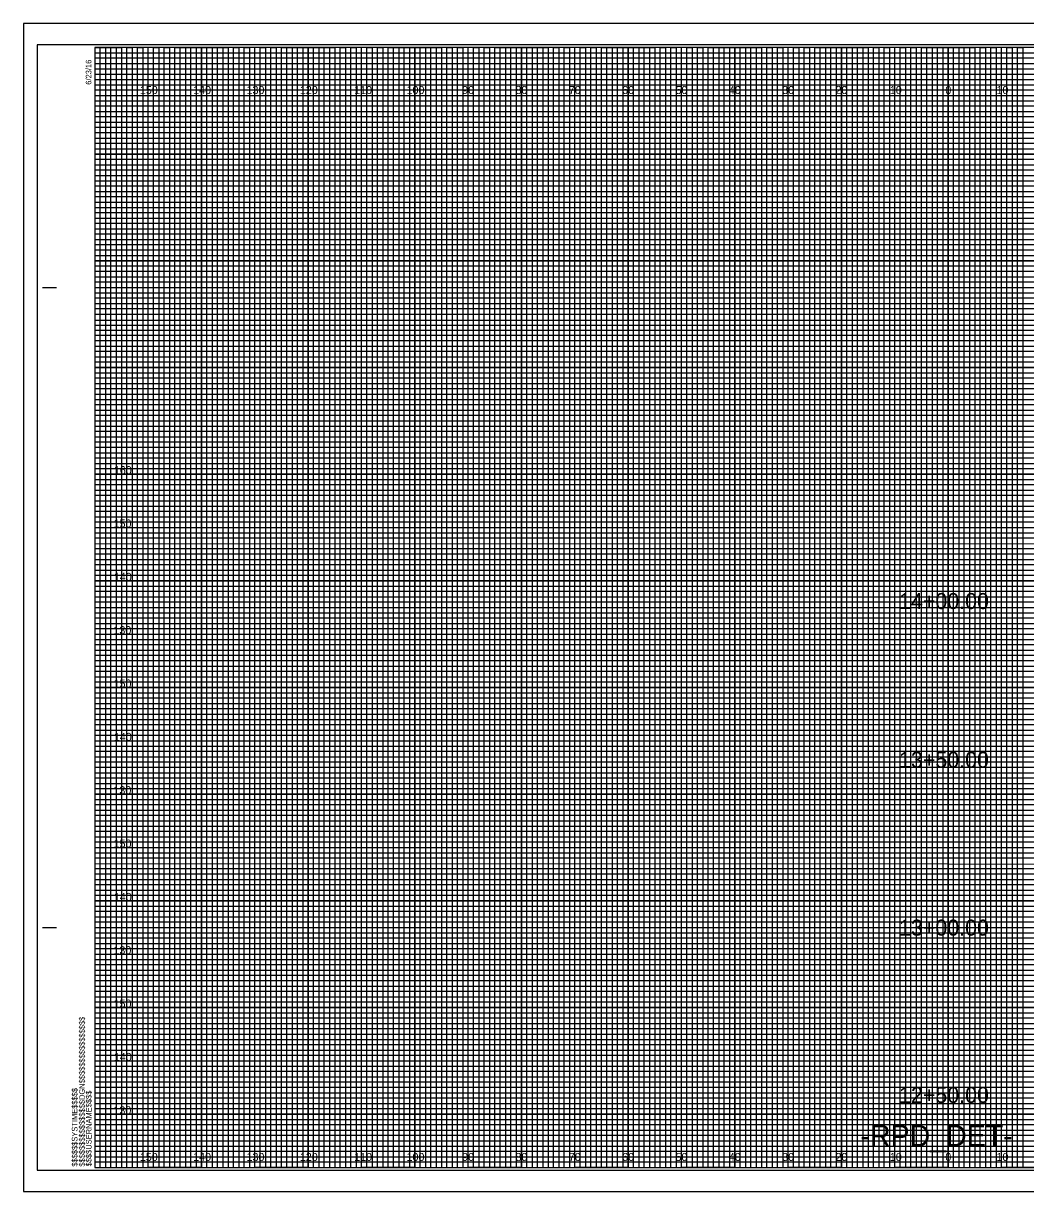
# Model space of a CAD drawing. Extents: x -13 to 323, y -5 to 434.
# Drawn here: x -13.4 to 174.5, y 215.5 to 434.5 of the extents above; entities that cross this region are included whole.
import ezdxf

# ---------------------------------------------------------------- set-up
doc = ezdxf.new("R2010")
doc.units = 0
for name, color, linetype in [('Exist Cross Section Cell', 7, 'Continuous'), ('Exist XS Center Line Elevation Label', 7, 'Continuous'), ('Exist XS Ground Line', 7, 'Continuous'), ('Prop CMT Pvmt Course 1', 7, 'Continuous'), ('Prop CMT Pvmt Course 3', 7, 'Continuous'), ('Prop CMT Pvmt Surface', 7, 'Continuous'), ('Prop CMT Pvmt Surface Shoulder', 7, 'Continuous'), ('Prop CMT Shld Paved Course 1', 7, 'Continuous'), ('Prop CMT Shld Paved Course 2', 7, 'Continuous'), ('Prop CMT Shld Paved Course 3', 7, 'Continuous'), ('Prop CMT Slope Grass', 7, 'Continuous'), ('Prop CMT Subgrade Earthwork', 7, 'Continuous'), ('Scratch_Level_1', 7, 'Continuous')]:
    doc.layers.add(name, color=color, linetype=linetype)

msp = doc.modelspace()

# ---------------------------------------------------------------- linework, layer by layer
at = {"layer": 'Exist XS Center Line Elevation Label'}
for points in [[(0, 430), (5, 430), (5, 220), (15, 220), (15, 430), (25, 430), (25, 220), (35, 220), (35, 430), (45, 430), (45, 220), (55, 220), (55, 430), (65, 430), (65, 220), (75, 220), (75, 430), (85, 430), (85, 220), (95, 220), (95, 430), (105, 430), (105, 220), (115, 220), (115, 430), (125, 430), (125, 220), (135, 220), (135, 430), (145, 430), (145, 220), (155, 220), (155, 430), (165, 430), (165, 220), (175, 220)], [(0, 425), (275, 425)], [(0, 405), (320, 405), (320, 415), (0, 415)], [(0, 385), (320, 385), (320, 395), (0, 395)], [(0, 365), (320, 365), (320, 375), (0, 375)], [(0, 345), (320, 345), (320, 355), (0, 355)], [(0, 325), (320, 325), (320, 335), (0, 335)], [(0, 305), (320, 305), (320, 315), (0, 315)], [(0, 285), (320, 285), (320, 295), (0, 295)], [(0, 265), (320, 265), (320, 275), (0, 275)], [(0, 245), (320, 245), (320, 255), (0, 255)], [(0, 225), (320, 225), (320, 235), (0, 235)]]:
    msp.add_lwpolyline(points, dxfattribs=at)
at = {"layer": 'Exist XS Ground Line'}
for p, q in [((10, 430), (0, 430)), ((10, 220), (10, 430)), ((30, 430), (20, 430)), ((20, 430), (20, 220)), ((30, 220), (30, 430)), ((50, 430), (40, 430)), ((40, 430), (40, 220)), ((50, 220), (50, 430)), ((70, 430), (60, 430)), ((60, 430), (60, 220)), ((70, 220), (70, 430)), ((90, 430), (80, 430)), ((80, 430), (80, 220)), ((90, 220), (90, 430)), ((110, 430), (100, 430)), ((100, 430), (100, 220)), ((110, 220), (110, 430)), ((130, 430), (120, 430)), ((120, 430), (120, 220)), ((130, 220), (130, 430)), ((150, 430), (140, 430)), ((140, 430), (140, 220)), ((150, 220), (150, 430)), ((170, 430), (160, 430)), ((160, 430), (160, 220)), ((170, 220), (170, 430)), ((20, 220), (10, 220)), ((40, 220), (30, 220)), ((60, 220), (50, 220)), ((80, 220), (70, 220)), ((100, 220), (90, 220)), ((120, 220), (110, 220)), ((140, 220), (130, 220)), ((160, 220), (150, 220)), ((180, 220), (170, 220))]:
    msp.add_line(p, q, dxfattribs=at)
for points in [[(0, 420), (320, 420), (320, 410), (0, 410)], [(0, 400), (320, 400), (320, 390), (0, 390)], [(0, 380), (320, 380), (320, 370), (0, 370)], [(0, 360), (320, 360), (320, 350), (0, 350)], [(0, 340), (320, 340), (320, 330), (0, 330)], [(0, 320), (320, 320), (320, 310), (0, 310)], [(0, 300), (320, 300), (320, 290), (0, 290)], [(0, 280), (320, 280), (320, 270), (0, 270)], [(0, 260), (320, 260), (320, 250), (0, 250)], [(0, 240), (320, 240), (320, 230), (0, 230)]]:
    msp.add_lwpolyline(points, dxfattribs=at)
at = {"layer": 'Prop CMT Pvmt Course 3'}
msp.add_lwpolyline([(-13.4, 215.5), (323.3, 215.5), (323.3, 434.5), (-13.4, 434.5)], close=True, dxfattribs=at)
at = {"layer": 'Prop CMT Pvmt Surface'}
for p, q in [((10, 220), (10, 430)), ((20, 220), (20, 430)), ((30, 220), (30, 430)), ((40, 220), (40, 430)), ((50, 220), (50, 430)), ((60, 220), (60, 430)), ((70, 220), (70, 430)), ((80, 220), (80, 430)), ((90, 220), (90, 430)), ((100, 220), (100, 430)), ((110, 220), (110, 430)), ((120, 220), (120, 430)), ((130, 220), (130, 430)), ((140, 220), (140, 430)), ((150, 220), (150, 430)), ((160, 220), (160, 430)), ((170, 220), (170, 430)), ((0, 420), (320, 420)), ((0, 410), (320, 410)), ((0, 400), (320, 400)), ((0, 390), (320, 390)), ((0, 380), (320, 380)), ((0, 370), (320, 370)), ((0, 360), (320, 360)), ((0, 350), (320, 350)), ((0, 340), (320, 340)), ((0, 330), (320, 330)), ((0, 320), (320, 320)), ((0, 310), (320, 310)), ((0, 300), (320, 300)), ((0, 290), (320, 290)), ((0, 280), (320, 280)), ((0, 270), (320, 270)), ((0, 260), (320, 260)), ((0, 250), (320, 250)), ((0, 240), (320, 240)), ((0, 230), (320, 230))]:
    msp.add_line(p, q, dxfattribs=at)
at = {"layer": 'Prop CMT Pvmt Surface Shoulder'}
for p, q in [((323.3, 434.5), (-13.4, 434.5)), ((-13.4, 434.5), (-13.4, 215.5)), ((-13.4, 215.5), (323.3, 215.5))]:
    msp.add_line(p, q, dxfattribs=at)
at = {"layer": 'Prop CMT Shld Paved Course 1'}
for p, q in [((0, 429), (260, 429)), ((260, 427.98), (0, 427.98)), ((0, 427.98), (0, 427)), ((0, 427), (260, 427)), ((260, 425.89), (0, 425.89)), ((0, 425.89), (0, 424)), ((0, 424), (320, 424))]:
    msp.add_line(p, q, dxfattribs=at)
for points in [[(0, 423), (270, 423), (320, 423), (320, 422), (0, 422)], [(0, 421), (320, 421), (320, 419), (0, 419)], [(0, 418), (320, 418), (320, 417), (0, 416.98)], [(0, 416), (320, 416), (320, 414), (0, 414)], [(0, 413), (320, 413), (320, 412), (0, 412)], [(0, 411), (320, 411), (320, 409), (0, 409)], [(0, 408), (320, 408), (320, 407), (0, 407)], [(0, 406), (320, 406), (320, 404), (0, 404)], [(0, 403), (320, 403), (320, 402), (0, 402)], [(0, 401), (320, 401), (320, 399), (0, 399)], [(0, 398), (320, 398), (320, 397), (0, 397)], [(0, 396), (320, 396), (320, 393.95), (320, 393), (320, 392), (0, 392)], [(0, 394), (320, 394), (320, 393), (0, 393)], [(0, 391), (320, 391), (320, 389), (0, 389.03)], [(0, 389.03), (320, 389), (320, 388), (0, 388)], [(0, 387), (320, 387), (320, 386), (0, 386)], [(0, 384), (320, 384), (320, 383), (0, 383)], [(0, 382), (320, 382), (320, 381), (0, 381)], [(-0.07, 378.89), (320, 378.89), (320, 377.88), (-0.07, 377.88)], [(0, 377), (320, 377), (320, 376), (0, 376)], [(0, 374), (320, 374), (320, 373), (0, 373)], [(0, 372), (320, 372), (320, 371), (0, 371)], [(0, 369), (320, 369), (320, 368), (0, 368)], [(0, 367), (320, 367), (320, 366), (0, 366)], [(0, 364), (320, 364), (320, 363), (0, 363)], [(0, 362), (320, 362), (320, 361), (0, 361)], [(0, 359), (320, 359), (319.99, 357.98), (0, 358)], [(0, 357), (320, 357), (320, 356), (0, 356)], [(0, 354), (320, 354), (320, 353), (0, 353)], [(0, 352), (320, 352), (320, 351), (0, 351)], [(0, 349), (320, 349), (320, 348), (0, 348)], [(0, 347), (320, 347), (320, 346), (0, 346)], [(0, 344), (320, 344), (320, 343), (0, 343)], [(0, 342), (320, 342), (320, 341), (0, 341)], [(0, 339), (320, 339), (320, 338), (0, 338)], [(0, 336.99), (320.07, 336.91), (320, 336), (0, 336)], [(0, 334), (320, 334), (320, 333), (0, 333)], [(0, 332), (320, 332), (320, 331), (0, 331)], [(0, 329), (320, 329), (320, 328), (0, 328)], [(0, 327), (320, 327), (320, 326), (0, 326)], [(0, 324), (320, 324), (320, 323), (0, 323)], [(0, 322), (320, 322), (320, 321), (0, 321)], [(0, 319), (320, 319), (320, 318), (0, 318)], [(0, 317), (320, 317), (320, 316), (0, 316)], [(0, 314), (320, 314), (320, 313), (0, 313)], [(0, 312), (320, 312), (320, 311), (0, 311)], [(0, 309), (320, 309), (320, 308), (0, 308)], [(0, 307), (320, 307), (320, 306), (0, 306)], [(0, 304), (320, 304), (320, 303), (0, 303)], [(0, 302), (320, 302), (320, 301), (0, 301)], [(0, 299), (320, 299), (319.99, 297.98), (0, 298)], [(0, 297), (320, 297), (320, 296), (0, 296)], [(0, 294), (320, 294), (320, 293), (0, 293)], [(0, 292), (320, 292), (320, 291), (0, 291)], [(0, 289), (320, 289), (320, 288), (0, 288)], [(0, 287), (320, 287), (320, 286), (0, 286)], [(0, 284), (320, 284), (320, 283), (0, 283)], [(0, 282), (320, 282), (320, 281), (0, 281)], [(0, 279), (320, 279), (320, 278), (0, 278)], [(0, 276.99), (320.07, 276.91), (320, 276), (0, 276)], [(0, 274), (320, 274), (320, 273), (0, 273)], [(0, 272), (320, 272), (320, 271), (0, 271)], [(0, 269), (320, 269), (320, 268), (0, 268)], [(0, 267), (320, 267), (320, 266), (0, 266)], [(0, 264), (320, 264), (320, 263), (0, 263)], [(0, 262), (320, 262), (320, 261), (0, 261)], [(0, 259), (320, 259), (320, 258), (0, 258)], [(0, 257), (320, 257), (320, 256), (0, 256)], [(0, 254), (320, 254), (320, 253), (0, 253)], [(0, 252), (320, 252), (320, 251), (0, 251)], [(0, 249), (320, 249), (320, 248), (0, 248)], [(0, 247), (320, 247), (320, 246), (0, 246)], [(0, 244), (320, 244), (320, 243), (0, 243)], [(0, 242), (320, 242), (320, 241), (0, 241)], [(0, 239), (320, 239), (320, 238), (0, 238)], [(0, 237), (320, 237), (320, 236), (0, 236)], [(0, 234), (320, 234), (320, 233), (0, 233)], [(0, 232), (320, 232), (320, 231), (0, 231)], [(0, 229), (320, 229), (320, 228), (0, 228)], [(0, 227), (320, 227), (320, 226), (0, 226)], [(0, 224), (320, 224), (320, 223), (0, 223)], [(0, 222), (320, 222), (320, 221), (0, 221)]]:
    msp.add_lwpolyline(points, dxfattribs=at)
at = {"layer": 'Prop CMT Shld Paved Course 2'}
for p, q in [((-9.8, 385), (-7.3, 385)), ((-9.7, 385), (-7.2, 385)), ((-9.8, 265), (-7.3, 265)), ((-9.7, 265), (-7.2, 265)), ((0, 220), (0, 220)), ((0, 220), (0, 220)), ((0, 220), (0, 220)), ((0, 220), (0, 220)), ((0, 220), (0, 220)), ((0, 220), (0, 220)), ((0, 220), (0, 220))]:
    msp.add_line(p, q, dxfattribs=at)
msp.add_lwpolyline([(320, 430), (0, 430), (0, 220), (320, 220)], close=True, dxfattribs=at)
at = {"layer": 'Prop CMT Shld Paved Course 3'}
for points in [[(0, 220), (1, 220), (1, 430), (2, 430), (2, 220)], [(2, 220), (3, 220), (3, 430), (4, 430), (4, 220)], [(5, 220), (6, 220), (6, 430), (7, 430), (7, 220)], [(7, 220), (8, 220), (8, 430), (9, 430), (9, 220)], [(10, 220), (11, 220), (11, 430), (12, 430), (12, 220)], [(12, 220), (13, 220), (13, 430), (14, 430), (14, 220)], [(15, 220), (16, 220), (16, 430), (17, 430), (17, 220)], [(17, 220), (18, 220), (18, 430), (19, 430), (19, 220)], [(20, 220), (21, 220), (21, 430), (22, 430), (22, 220)], [(22, 220), (23, 220), (23, 430), (24, 430), (24, 220)], [(25, 220), (26, 220), (26, 430), (27, 430), (27, 220)], [(27, 220), (28, 220), (28, 430), (29, 430), (29, 220)], [(30, 220), (31, 220), (31, 430), (32, 430), (32, 220)], [(32, 220), (33, 220), (33, 430), (34, 430), (34, 220)], [(35, 220), (36, 220), (36, 430), (37, 430), (37, 220)], [(37, 220), (38, 220), (38, 430), (39, 430), (39, 220)], [(40, 220), (41, 220), (41, 430), (42, 430), (42, 220)], [(42, 220), (43, 220), (43, 430), (44, 430), (44, 220)], [(45, 220), (46, 220), (46, 430), (47, 430), (47, 220)], [(47, 220), (48, 220), (48, 430), (49, 430), (49, 220)], [(50, 220), (51, 220), (51, 430), (52, 430), (52, 220)], [(52, 220), (53, 220), (53, 430), (54, 430), (54, 220)], [(55, 220), (56, 220), (56, 430), (57, 430), (57, 220)], [(57, 220), (58, 220), (58, 430), (59, 430), (59, 220)], [(60, 220), (61, 220), (61, 430), (62, 430), (62, 220)], [(62, 220), (63, 220), (63, 430), (64, 430), (64, 220)], [(65, 220), (66, 220), (66, 430), (67, 430), (67, 220)], [(67, 220), (68, 220), (68, 430), (69, 430), (69, 220)], [(70, 220), (71, 220), (71, 430), (72, 430), (72, 220)], [(72, 220), (73, 220), (73, 430), (74, 430), (74, 220)], [(75, 220), (76, 220), (76, 430), (77, 430), (77, 220)], [(77, 220), (78, 220), (78, 430), (79, 430), (79, 220)], [(80, 220), (81, 220), (81, 430), (82, 430), (82, 220)], [(82, 220), (83, 220), (83, 430), (84, 430), (84, 220)], [(85, 220), (86, 220), (86, 430), (87, 430), (87, 220)], [(87, 220), (88, 220), (88, 430), (89, 430), (89, 220)], [(90, 220), (91, 220), (91, 430), (92, 430), (92, 220)], [(92, 220), (93, 220), (93, 430), (94, 430), (94, 220)], [(95, 220), (96, 220), (96, 430), (97, 430), (97, 220)], [(97, 220), (98, 220), (98, 430), (99, 430), (99, 220)], [(100, 220), (101, 220), (101, 430), (102, 430), (102, 220)], [(102, 220), (103, 220), (103, 430), (104, 430), (104, 220)], [(105, 220), (106, 220), (106, 430), (107, 430), (107, 220)], [(107, 220), (108, 220), (108, 430), (109, 430), (109, 220)], [(110, 220), (111, 220), (111, 430), (112, 430), (112, 220)], [(112, 220), (113, 220), (113, 430), (114, 430), (114, 220)], [(115, 220), (116, 220), (116, 430), (117, 430), (117, 220)], [(117, 220), (118, 220), (118, 430), (119, 430), (119, 220)], [(120, 220), (121, 220), (121, 430), (122, 430), (122, 220)], [(122, 220), (123, 220), (123, 430), (124, 430), (124, 220)], [(125, 220), (126, 220), (126, 430), (127, 430), (127, 220)], [(127, 220), (128, 220), (128, 430), (129, 430), (129, 220)], [(130, 220), (131, 220), (131, 430), (132, 430), (132, 220)], [(132, 220), (133, 220), (133, 430), (134, 430), (134, 220)], [(135, 220), (136, 220), (136, 430), (137, 430), (137, 220)], [(137, 220), (138, 220), (138, 430), (139, 430), (139, 220)], [(140, 220), (141, 220), (141, 430), (142, 430), (142, 220)], [(142, 220), (143, 220), (143, 430), (144, 430), (144, 220)], [(145, 220), (146, 220), (146, 430), (147, 430), (147, 220)], [(147, 220), (148, 220), (148, 430), (149, 430), (149, 220)], [(150, 220), (151, 220), (151, 430), (152, 430), (152, 220)], [(152, 220), (153, 220), (153, 430), (154, 430), (154, 220)], [(155, 220), (156, 220), (156, 430), (157, 430), (157, 220)], [(157, 220), (158, 220), (158, 430), (159, 430), (159, 220)], [(160, 220), (161, 220), (161, 430), (162, 430), (162, 220)], [(162, 220), (163, 220), (163, 430), (164, 430), (164, 220)], [(165, 220), (166, 220), (166, 430), (167, 430), (167, 220)], [(167, 220), (168, 220), (168, 430), (169, 430), (169, 220)], [(170, 220), (171, 220), (171, 430), (172, 430), (172, 220)], [(172, 220), (173, 220), (173, 430), (174, 430), (174, 220)]]:
    msp.add_lwpolyline(points, dxfattribs=at)
at = {"layer": 'Prop CMT Subgrade Earthwork'}
msp.add_lwpolyline([(-10.8, 219.5), (322.4, 219.5), (322.4, 430.5), (-10.8, 430.5)], close=True, dxfattribs=at)

# ---------------------------------------------------------------- texts
at = {"layer": 'Exist Cross Section Cell'}
for s, p in [('150', (8.44, 421.25)), ('140', (18.44, 421.25)), ('130', (28.44, 421.25)), ('120', (38.44, 421.25)), ('110', (48.62, 421.25)), ('100', (58.44, 421.25)), ('90', (68.86, 421.25)), ('80', (78.86, 421.25)), ('70', (88.86, 421.25)), ('60', (98.86, 421.25)), ('50', (108.86, 421.25)), ('40', (118.86, 421.25)), ('30', (128.86, 421.25)), ('20', (138.86, 421.25)), ('10', (149.04, 421.25)), ('0', (159.45, 421.25)), ('0', (159.45, 421.25)), ('10', (169.04, 421.25)), ('150', (8.44, 221.25)), ('140', (18.44, 221.25)), ('130', (28.44, 221.25)), ('120', (38.44, 221.25)), ('110', (48.62, 221.25)), ('100', (58.44, 221.25)), ('90', (68.86, 221.25)), ('80', (78.86, 221.25)), ('70', (88.86, 221.25)), ('60', (98.86, 221.25)), ('50', (108.86, 221.25)), ('40', (118.86, 221.25)), ('30', (128.86, 221.25)), ('20', (138.86, 221.25)), ('10', (149.04, 221.25)), ('0', (159.45, 221.25)), ('0', (159.45, 221.25)), ('10', (169.04, 221.25))]:
    msp.add_text(s, height=1.5, dxfattribs=at).set_placement(p)
at = {"layer": 'Prop CMT Pvmt Course 1'}
for s, p in [('160', (3.57, 350)), ('150', (3.52, 340)), ('140', (3.57, 330)), ('130', (3.49, 320)), ('150', (3.52, 310)), ('140', (3.57, 300)), ('130', (3.49, 290)), ('150', (3.52, 280)), ('140', (3.57, 270)), ('130', (3.49, 260)), ('150', (3.52, 250)), ('140', (3.57, 240)), ('130', (3.49, 230))]:
    msp.add_text(s, height=1.5, dxfattribs=at).set_placement(p)
at = {"layer": 'Prop CMT Shld Paved Course 2'}
for s, p in [('6/23/16', (-0.65, 423)), ('$$$$$$$$$$$$$$$$DGN$$$$$$$$$$$$$$$$', (-1.88, 220.18)), ('$$$$$$SYSTIME$$$$$', (-3.26, 220.18)), ('$$$$USERNAME$$$$', (-0.62, 220.23))]:
    msp.add_text(s, height=1.05, rotation=90, dxfattribs=at).set_placement(p)
at = {"layer": 'Prop CMT Slope Grass'}
for s, p in [('14+00.00', (150.77, 324.71)), ('13+50.00', (150.77, 294.96)), ('13+00.00', (150.77, 263.49)), ('12+50.00', (150.77, 232.13))]:
    msp.add_text(s, height=3, dxfattribs=at).set_placement(p)
at = {"layer": 'Scratch_Level_1'}
msp.add_text('-RPD_DET-', height=4, dxfattribs=at).set_placement((143.54, 224))

doc.saveas('drawing.dxf')
